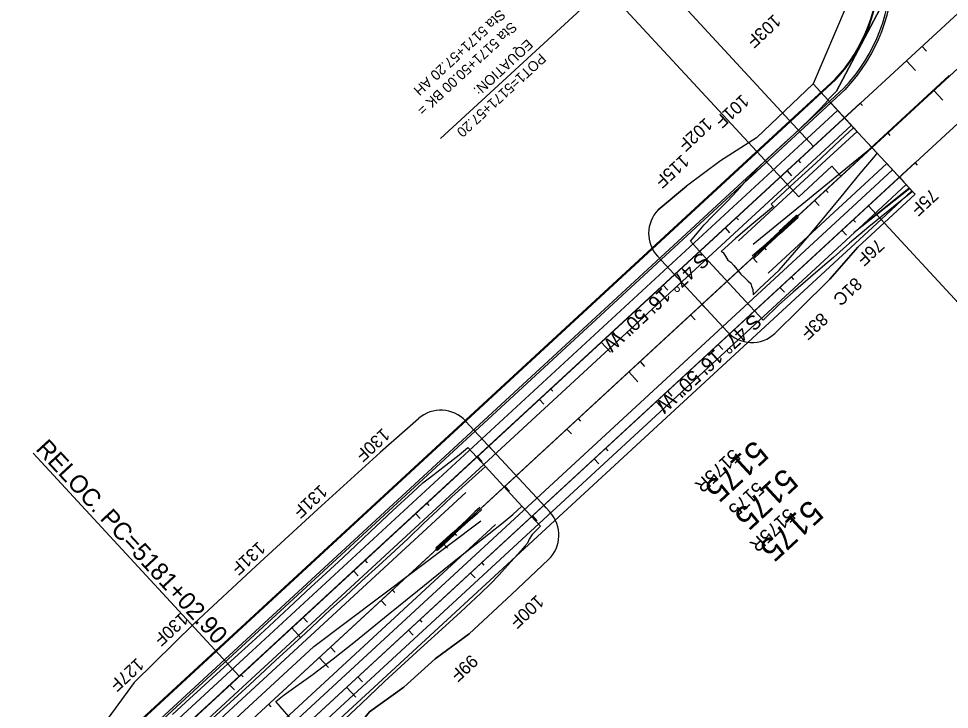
# Model space of a CAD drawing. Extents: x 2160876 to 2175990, y 601436 to 618246.
# Drawn here: x 2171264 to 2172369, y 613107 to 613927 of the extents above; entities that cross this region are included whole.
import ezdxf

# ---------------------------------------------------------------- set-up
doc = ezdxf.new("R2010")
doc.units = 0
for name, color, linetype in [('BNDY-ADJ', 7, 'Continuous'), ('BNDY-ADJ-TXT', 7, 'Continuous'), ('EX-UTIL-ELEC-TXT', 7, 'Continuous'), ('GN_Transparent 80', 7, 'Continuous'), ('RD_DTM_Major2', 7, 'Continuous'), ('RD_EX_BldgApp_Deck', 7, 'Continuous'), ('RD_EX_BldgApp_Sign', 7, 'Continuous'), ('RD_EX_BldgApp_Steps', 7, 'Continuous'), ('RD_EX_DV_TX_Prop', 7, 'Continuous'), ('RD_EX_Fence_Gate', 7, 'Continuous'), ('RD_EX_Parking_Conc', 7, 'Continuous'), ('RD_EX_RW', 7, 'Continuous'), ('RD_HC_Cl', 7, 'Continuous'), ('RD_HC_Data_Tic', 7, 'Continuous'), ('RD_HC_TX_Sta50', 7, 'Continuous'), ('RD_TX_RoadID', 7, 'Continuous')]:
    doc.layers.add(name, color=color, linetype=linetype)

msp = doc.modelspace()

# ---------------------------------------------------------------- linework, layer by layer
at = {"layer": 'BNDY-ADJ'}
for p, q in [((2172654, 614122.3), (2172239.9, 613739.9)), ((2172239.9, 613739.9), (2163704.8, 605858.6))]:
    msp.add_line(p, q, dxfattribs=at)
at = {"layer": 'BNDY-ADJ-TXT'}
for p, q in [((2172621.5, 614157.6), (2172207.3, 613775.1)), ((2172686.6, 614087), (2172272.5, 613704.6)), ((2172207.3, 613775.1), (2170395.2, 612101.8)), ((2172272.5, 613704.6), (2170460.3, 612031.3))]:
    msp.add_line(p, q, dxfattribs=at)
at = {"layer": 'EX-UTIL-ELEC-TXT'}
for p, q in [((2172233, 613855.1), (2172179.3, 613805.5)), ((2172233.7, 613854.4), (2172180, 613804.8)), ((2172235.9, 613817.9), (2172199.2, 613784)), ((2172179.3, 613805.5), (2170367.1, 612132.2)), ((2172244.1, 613809.1), (2172207.3, 613775.1)), ((2172180, 613804.8), (2170367.8, 612131.4)), ((2172252.2, 613800.2), (2172215.5, 613766.3)), ((2172199.2, 613784), (2170387, 612110.6)), ((2172207.3, 613775.1), (2170395.2, 612101.8)), ((2172215.5, 613766.3), (2170403.3, 612093)), ((2172301, 613747.3), (2172264.3, 613713.4)), ((2172317.3, 613729.7), (2172261.1, 613677.8)), ((2172309.2, 613738.5), (2172272.5, 613704.6)), ((2172321.6, 613725.1), (2172255.3, 613672.4)), ((2172264.3, 613713.4), (2170452.2, 612040.1)), ((2172272.5, 613704.6), (2170460.3, 612031.3)), ((2172261.1, 613677.8), (2170468.4, 612022.5))]:
    msp.add_line(p, q, dxfattribs=at)
msp.add_lwpolyline([(2172261.1, 613677.8), (2172306.9, 613714.8), (2172320.8, 613726)], dxfattribs=at)
for radius, start in [(193, 316.7496), (194, 317.041), (208, 316.7496)]:
    msp.add_arc((2172091.8, 613986.7), radius, start, 1.4209, dxfattribs=at)
at = {"layer": 'GN_Transparent 80'}
for p, q in [((2172243.2, 613844.1), (2172189.5, 613794.5)), ((2172244.9, 613842.5), (2172191, 613792.8)), ((2172189.5, 613794.5), (2170377.3, 612121.1)), ((2172191, 613792.8), (2170378.9, 612119.4)), ((2172150.6, 613659), (2172166.8, 613673.9)), ((2172168.3, 613672.2), (2172166.8, 613673.9)), ((2172152.2, 613657.3), (2172168.3, 613672.2)), ((2172142.8, 613647.8), (2172152.2, 613657.3)), ((2172137, 613642.3), (2172142.8, 613647.8)), ((2171813.7, 613343.8), (2171807.8, 613338.4)), ((2171796, 613331.6), (2171779.8, 613316.6)), ((2171807.8, 613338.4), (2171797.6, 613329.8)), ((2171797.6, 613329.8), (2171781.4, 613314.9)), ((2171781.4, 613314.9), (2171779.8, 613316.6))]:
    msp.add_line(p, q, dxfattribs=at)
for points in [[(2172134.5, 613645), (2172140.3, 613650.5), (2172150.6, 613659)], [(2171811.2, 613346.5), (2171805.3, 613341.1), (2171796, 613331.6)]]:
    msp.add_lwpolyline(points, dxfattribs=at)
msp.add_arc((2172091.8, 613986.7), 210.3, 316.7048, 1.4209, dxfattribs=at)
at = {"layer": 'RD_DTM_Major2'}
for p, q in [((2172350.1, 613841.6), (2172360.9, 613829.9)), ((2172276.6, 613773.8), (2172282, 613767.9)), ((2172208.4, 613710.8), (2172213.9, 613705)), ((2172135, 613643), (2172140.4, 613637.1)), ((2172061.5, 613575.2), (2172066.9, 613569.3)), ((2171988, 613507.3), (2171998.9, 613495.6)), ((2171914.6, 613439.5), (2171920, 613433.6)), ((2171841.1, 613371.6), (2171846.5, 613365.8)), ((2171767.6, 613303.8), (2171773.1, 613297.9)), ((2171694.2, 613236), (2171699.6, 613230.1)), ((2171620.7, 613168.1), (2171631.6, 613156.4))]:
    msp.add_line(p, q, dxfattribs=at)
at = {"layer": 'RD_EX_BldgApp_Deck'}
for p, q in [((2172166.4, 613674.3), (2172186.3, 613692.6)), ((2172166.4, 613674.3), (2172186.3, 613692.6)), ((2172168.7, 613671.9), (2172188.5, 613690.2)), ((2172188.5, 613690.2), (2172168.7, 613671.9)), ((2172169.7, 613676.6), (2172186.6, 613692.3)), ((2172171.3, 613674.9), (2172188.2, 613690.5)), ((2172177.8, 613684.1), (2172175.9, 613682.3)), ((2172178.1, 613684.4), (2172177.8, 613684.1)), ((2172179.4, 613682.4), (2172177.8, 613684.1)), ((2172180, 613686.1), (2172178.1, 613684.4)), ((2172179.7, 613682.7), (2172178.1, 613684.4)), ((2172180.3, 613686.4), (2172180, 613686.1)), ((2172181.6, 613684.4), (2172180, 613686.1)), ((2172182.2, 613688.2), (2172180.3, 613686.4)), ((2172181.9, 613684.7), (2172180.3, 613686.4)), ((2172182.5, 613688.5), (2172182.2, 613688.2)), ((2172183.8, 613686.5), (2172182.2, 613688.2)), ((2172184.4, 613690.2), (2172182.5, 613688.5)), ((2172184.1, 613686.7), (2172182.5, 613688.5)), ((2172186, 613688.5), (2172184.4, 613690.2)), ((2172186.3, 613688.8), (2172184.7, 613690.5)), ((2172188.5, 613690.2), (2172186.3, 613692.6)), ((2172186.5, 613692.3), (2172186.3, 613692.6)), ((2172188.5, 613690.2), (2172188.2, 613690.5)), ((2172166.4, 613674.3), (2172166.8, 613673.9)), ((2172166.8, 613673.9), (2172166.4, 613674.3)), ((2172166.8, 613673.9), (2172169.7, 613676.6)), ((2172169.7, 613676.6), (2172166.8, 613673.9)), ((2172168.3, 613672.2), (2172171.3, 613674.9)), ((2172168.3, 613672.2), (2172171.3, 613674.9)), ((2172171.2, 613678), (2172169.7, 613676.6)), ((2172171.3, 613674.9), (2172169.7, 613676.6)), ((2172171.5, 613678.3), (2172171.2, 613678)), ((2172172.7, 613676.3), (2172171.2, 613678)), ((2172173.4, 613680), (2172171.5, 613678.3)), ((2172173, 613676.6), (2172171.5, 613678.3)), ((2172173.7, 613680.3), (2172173.4, 613680)), ((2172174.9, 613678.3), (2172173.4, 613680)), ((2172175.6, 613682.1), (2172173.7, 613680.3)), ((2172175.2, 613678.6), (2172173.7, 613680.3)), ((2172175.9, 613682.3), (2172175.6, 613682.1)), ((2172177.2, 613680.4), (2172175.6, 613682.1)), ((2172177.4, 613680.6), (2172175.9, 613682.3)), ((2172168.7, 613671.9), (2172168.3, 613672.2)), ((2172168.7, 613671.9), (2172168.3, 613672.2)), ((2171779.5, 613317), (2171759.6, 613298.7)), ((2171779.5, 613317), (2171759.6, 613298.7)), ((2171776.9, 613313.9), (2171760, 613298.3)), ((2171778.5, 613312.2), (2171761.6, 613296.6)), ((2171781.7, 613314.6), (2171761.9, 613296.2)), ((2171761.9, 613296.2), (2171781.7, 613314.6)), ((2171770.7, 613308.2), (2171771, 613308.5)), ((2171771, 613308.5), (2171772.9, 613310.3)), ((2171772.6, 613306.8), (2171771, 613308.5)), ((2171772.9, 613310.3), (2171773.2, 613310.5)), ((2171774.5, 613308.5), (2171772.9, 613310.3)), ((2171773.2, 613310.5), (2171775.1, 613312.3)), ((2171774.8, 613308.8), (2171773.2, 613310.5)), ((2171775.1, 613312.3), (2171775.4, 613312.6)), ((2171776.7, 613310.6), (2171775.1, 613312.3)), ((2171775.4, 613312.6), (2171776.9, 613313.9)), ((2171777, 613310.9), (2171775.4, 613312.6)), ((2171779.8, 613316.6), (2171776.9, 613313.9)), ((2171776.9, 613313.9), (2171779.8, 613316.6)), ((2171778.5, 613312.2), (2171776.9, 613313.9)), ((2171781.4, 613314.9), (2171778.5, 613312.2)), ((2171781.4, 613314.9), (2171778.5, 613312.2)), ((2171779.5, 613317), (2171779.8, 613316.6)), ((2171779.8, 613316.6), (2171779.5, 613317)), ((2171781.7, 613314.6), (2171781.4, 613314.9)), ((2171781.7, 613314.6), (2171781.4, 613314.9)), ((2171761.9, 613296.2), (2171759.6, 613298.7)), ((2171759.9, 613298.4), (2171759.6, 613298.7)), ((2171763.5, 613298.4), (2171761.9, 613300.1)), ((2171762.2, 613300.4), (2171764.1, 613302.1)), ((2171763.8, 613298.6), (2171762.2, 613300.4)), ((2171764.1, 613302.1), (2171764.4, 613302.4)), ((2171765.7, 613300.4), (2171764.1, 613302.1)), ((2171764.4, 613302.4), (2171766.3, 613304.2)), ((2171766, 613300.7), (2171764.4, 613302.4)), ((2171766.3, 613304.2), (2171766.6, 613304.4)), ((2171767.9, 613302.4), (2171766.3, 613304.2)), ((2171766.6, 613304.4), (2171768.5, 613306.2)), ((2171768.2, 613302.7), (2171766.6, 613304.4)), ((2171768.5, 613306.2), (2171768.8, 613306.5)), ((2171770.1, 613304.5), (2171768.5, 613306.2)), ((2171768.8, 613306.5), (2171770.7, 613308.2)), ((2171770.4, 613304.7), (2171768.8, 613306.5)), ((2171772.3, 613306.5), (2171770.7, 613308.2)), ((2171761.9, 613296.2), (2171761.6, 613296.5))]:
    msp.add_line(p, q, dxfattribs=at)
for points in [[(2172171.3, 613674.9), (2172172.7, 613676.3), (2172173, 613676.6), (2172174.9, 613678.3), (2172175.2, 613678.6), (2172177.2, 613680.4), (2172177.4, 613680.6), (2172179.4, 613682.4), (2172179.7, 613682.7), (2172181.6, 613684.4), (2172181.9, 613684.7), (2172183.8, 613686.5), (2172184.1, 613686.7), (2172186, 613688.5), (2172186.3, 613688.8), (2172188.2, 613690.5)], [(2172186.6, 613692.3), (2172184.7, 613690.5), (2172184.4, 613690.2)], [(2172186.3, 613692.6), (2172186.5, 613692.3), (2172186.6, 613692.3)], [(2172188.2, 613690.5), (2172188.2, 613690.5), (2172188.5, 613690.2)], [(2171778.5, 613312.2), (2171777, 613310.9), (2171776.7, 613310.6), (2171774.8, 613308.8), (2171774.5, 613308.5), (2171772.6, 613306.8), (2171772.3, 613306.5), (2171770.4, 613304.7), (2171770.1, 613304.5), (2171768.2, 613302.7), (2171767.9, 613302.4), (2171766, 613300.7), (2171765.7, 613300.4), (2171763.8, 613298.6), (2171763.5, 613298.4), (2171761.6, 613296.6)], [(2171759.6, 613298.7), (2171759.9, 613298.4), (2171760, 613298.3)], [(2171760, 613298.3), (2171761.9, 613300.1), (2171762.2, 613300.4)], [(2171761.6, 613296.6), (2171761.6, 613296.5), (2171761.9, 613296.2)]]:
    msp.add_lwpolyline(points, dxfattribs=at)
for centre, radius, start, end in [((2172187.4, 613691.4), 1.67, 312.7195, 132.7195), ((2172187.4, 613691.4), 1.67, 312.7195, 132.7195), ((2172187.4, 613691.4), 1.27, 312.7195, 132.7195), ((2172187.4, 613691.4), 1.27, 312.7195, 132.7195), ((2171760.8, 613297.5), 1.67, 132.7195, 312.7195), ((2171760.8, 613297.5), 1.67, 132.7195, 312.7195), ((2171760.8, 613297.5), 1.27, 132.7195, 312.7195), ((2171760.8, 613297.5), 1.27, 132.7195, 312.7195)]:
    msp.add_arc(centre, radius, start, end, dxfattribs=at)
at = {"layer": 'RD_EX_BldgApp_Sign'}
for p, q in [((2172368.3, 613859.5), (2172269.3, 613768)), ((2172269.3, 613768), (2172135.6, 613658.5)), ((2171614.4, 613181.4), (2171812.6, 613330.3)), ((2170418.2, 612076.8), (2171614.4, 613181.4))]:
    msp.add_line(p, q, dxfattribs=at)
at = {"layer": 'RD_EX_BldgApp_Steps'}
for p, q in [((2172672.7, 614139.6), (2163700.6, 605854.7)), ((2172336, 613894.3), (2172341.5, 613888.4)), ((2172262.6, 613826.5), (2171525.8, 613146.1)), ((2172262.6, 613826.5), (2172265.3, 613823.5)), ((2172295.3, 613791.1), (2172298, 613788.1)), ((2172327.8, 613755.9), (2171568.5, 613054.8)), ((2172189.1, 613758.6), (2172191.8, 613755.7)), ((2172327.8, 613755.8), (2172330.5, 613752.9)), ((2172221.9, 613723.2), (2172224.6, 613720.3)), ((2172115.6, 613690.8), (2172118.3, 613687.8)), ((2172254.3, 613688), (2172257, 613685.1)), ((2172148.4, 613655.4), (2172151.1, 613652.4)), ((2172042.2, 613622.9), (2172044.9, 613620)), ((2172180.8, 613620.2), (2172183.6, 613617.2)), ((2172074.9, 613587.5), (2172077.6, 613584.6)), ((2171968.7, 613555.1), (2171974.1, 613549.2)), ((2172107.4, 613552.3), (2172110.1, 613549.4)), ((2172001.5, 613519.7), (2172006.9, 613513.8)), ((2171895.2, 613487.3), (2171897.9, 613484.3)), ((2172033.9, 613484.5), (2172039.3, 613478.6)), ((2171928, 613451.9), (2171930.7, 613448.9)), ((2171821.8, 613419.4), (2171824.5, 613416.5)), ((2171281.4, 613410.7), (2171525.8, 613146.1)), ((2171960.4, 613416.6), (2171963.2, 613413.7)), ((2171854.5, 613384), (2171857.2, 613381.1)), ((2171748.3, 613351.6), (2171751, 613348.6)), ((2171887, 613348.8), (2171889.7, 613345.9)), ((2171781, 613316.2), (2171783.8, 613313.2)), ((2171674.8, 613283.7), (2171677.5, 613280.8)), ((2171813.5, 613281), (2171816.2, 613278)), ((2171707.6, 613248.3), (2171710.3, 613245.4)), ((2171601.4, 613215.9), (2171606.8, 613210)), ((2171740, 613213.1), (2171742.7, 613210.2)), ((2171634.1, 613180.5), (2171639.5, 613174.6)), ((2171527.9, 613148.1), (2171530.6, 613145.1)), ((2171666.6, 613145.3), (2171672, 613139.4)), ((2171560.6, 613112.7), (2171563.4, 613109.7))]:
    msp.add_line(p, q, dxfattribs=at)
msp.add_arc((2246150.8, 532330.8), 110000, 132.719474, 133.343763, dxfattribs=at)
at = {"layer": 'RD_EX_Fence_Gate'}
for p, q in [((2172206.8, 613849.4), (2172139.8, 613785.1)), ((2172139.8, 613785.1), (2172097, 613757.8)), ((2172292.9, 613756.2), (2172260.3, 613791.4)), ((2172097, 613757.8), (2172056.7, 613727.8)), ((2172022.8, 613699.6), (2172056.7, 613727.8)), ((2172259.7, 613655.3), (2172327.9, 613718.3)), ((2172327.9, 613718.3), (2172325.5, 613720.9)), ((2172259.7, 613655.3), (2172226.5, 613617.6)), ((2172104.8, 613555.2), (2172022.2, 613644.6)), ((2172226.5, 613617.6), (2172190.9, 613582.4)), ((2172190.9, 613582.4), (2172161.4, 613553)), ((2171738.6, 613451.8), (2171693, 613411.5)), ((2171894.6, 613340.6), (2171794.5, 613449)), ((2171693, 613411.5), (2171618.9, 613344.3)), ((2171618.9, 613344.3), (2171545.4, 613276.7)), ((2171545.4, 613276.7), (2171472.5, 613208.6)), ((2171892.7, 613284.4), (2171848.8, 613242.9)), ((2171848.8, 613242.9), (2171798.8, 613196.4)), ((2171472.5, 613208.6), (2171401.2, 613138.6)), ((2171401.2, 613138.6), (2171341.1, 613056.4))]:
    msp.add_line(p, q, dxfattribs=at)
for points in [[(2172336.3, 614172), (2172273.2, 614089.5), (2172250.2, 614008.7), (2172246, 613941.4), (2172206.8, 613849.4)], [(2171798.8, 613196.4), (2171758.2, 613166.6), (2171721.2, 613133), (2171680.3, 613103.5), (2171648.3, 613064.5), (2171606.8, 613035.7)]]:
    msp.add_lwpolyline(points, dxfattribs=at)
for centre, start, end in [((2172051.6, 613671.8), 135.9419, 222.7195), ((2172134.2, 613582.3), 222.7195, 312.9079), ((2171765.1, 613421.9), 42.7195, 131.5105), ((2171865.2, 613313.5), 313.372, 42.7195)]:
    msp.add_arc(centre, 40, start, end, dxfattribs=at)
at = {"layer": 'RD_EX_Parking_Conc'}
for p, q in [((2171959.5, 613964.4), (2171764.8, 613784.6)), ((2172239.9, 613739.9), (2172229.2, 613751.5))]:
    msp.add_line(p, q, dxfattribs=at)
msp.add_lwpolyline([(2172229.2, 613751.5), (2172189.7, 613715.1), (2171959.5, 613964.4)], dxfattribs=at)
at = {"layer": 'RD_EX_RW'}
for p, q in [((2172206.8, 613849.4), (2172139.8, 613785.1)), ((2172260.3, 613791.4), (2172206.8, 613849.4)), ((2172224.5, 613830.2), (2172206.8, 613849.4)), ((2172206.8, 613849.4), (2172224.5, 613830.2)), ((2172254.9, 613797.3), (2172238.9, 613782.5)), ((2172260.3, 613791.4), (2172254.9, 613797.3)), ((2172139.8, 613785.1), (2172097, 613757.8)), ((2172283, 613766.9), (2172260.3, 613791.4)), ((2172097, 613757.8), (2172056.7, 613727.8)), ((2172325.5, 613720.9), (2172292.9, 613756.2)), ((2172056.7, 613727.8), (2172022.8, 613699.6)), ((2172259.7, 613655.3), (2172327.9, 613718.3)), ((2172325.5, 613720.9), (2172324.9, 613721.6)), ((2172327.9, 613718.3), (2172325.5, 613720.9)), ((2172226.5, 613617.6), (2172259.7, 613655.3)), ((2172022.2, 613644.6), (2172104.8, 613555.2)), ((2172190.9, 613582.4), (2172226.5, 613617.6)), ((2172161.4, 613553), (2172190.9, 613582.4)), ((2171738.6, 613451.8), (2171693, 613411.5)), ((2171894.6, 613340.6), (2171794.5, 613449)), ((2171693, 613411.5), (2171618.9, 613344.3)), ((2171861.3, 613347.9), (2171817.9, 613395)), ((2171618.9, 613344.3), (2171545.4, 613276.7)), ((2171545.4, 613276.7), (2171472.5, 613208.6)), ((2171848.8, 613242.9), (2171892.7, 613284.4)), ((2171798.8, 613196.4), (2171848.8, 613242.9)), ((2171472.5, 613208.6), (2171401.2, 613138.6)), ((2171401.2, 613138.6), (2171341.1, 613056.4))]:
    msp.add_line(p, q, dxfattribs=at)
for points in [[(2172349.7, 614161.7), (2172310.7, 614064.1), (2172297.2, 613959.5), (2172234.4, 613840.7)], [(2172234.4, 613840.7), (2172297.2, 613959.5), (2172310.7, 614064.1), (2172334.2, 614123)], [(2172263.8, 614056.5), (2172250.2, 614008.7), (2172246, 613941.4), (2172206.8, 613849.4)], [(2172224.5, 613830.2), (2172225.6, 613831.5), (2172234.4, 613840.7)], [(2172061.2, 613662.4), (2172071.8, 613674.8), (2172077.7, 613681.9), (2172087.1, 613692), (2172104.7, 613709.8), (2172117, 613722.9), (2172128.2, 613735.3), (2172141.5, 613749.8), (2172152.4, 613760.3), (2172172.8, 613779.2), (2172183.4, 613788.7), (2172202.7, 613807.1), (2172215.5, 613820), (2172224.5, 613830.2)], [(2172238.9, 613782.5), (2172209.9, 613755.4), (2172184.7, 613732.1), (2172157.2, 613706.5), (2172159.9, 613703.6), (2172131.8, 613680.5), (2172114.6, 613665.9), (2172097.6, 613650.4)], [(2172166.4, 613628.2), (2172184.9, 613649.1), (2172202.2, 613669.3), (2172223.3, 613694.5), (2172240.1, 613715.1), (2172262.5, 613742.8), (2172280.8, 613764.4), (2172283, 613766.9)], [(2172324.9, 613721.6), (2172310.7, 613710.1), (2172287.4, 613691.3), (2172273, 613679.7), (2172250.2, 613660.4), (2172231, 613643), (2172220.8, 613634.4), (2172203.8, 613619.8), (2172183, 613601.9), (2172166.3, 613587), (2172147.5, 613568.8)], [(2172147.5, 613568.8), (2172127, 613591.1), (2172082.8, 613638.9), (2172061.2, 613662.4)], [(2172147.5, 613568.8), (2172127, 613591.1), (2172082.8, 613638.9), (2172061.2, 613662.4)], [(2172097.6, 613650.4), (2172099.9, 613649), (2172103.2, 613643.8), (2172105.8, 613640.2), (2172109.2, 613637.5), (2172112.9, 613633.8), (2172116.4, 613629.4), (2172121.1, 613623.2), (2172125.8, 613619.1), (2172129.9, 613615.1), (2172132.9, 613612.2), (2172133.9, 613609.2), (2172135.1, 613605.3), (2172135.5, 613598.9)], [(2172135.5, 613598.9), (2172143.4, 613606.2), (2172166.4, 613628.2)], [(2171446.6, 613100.4), (2171462.4, 613115.2), (2171480.4, 613131.5), (2171499.2, 613148.8), (2171520.3, 613167.8), (2171540.7, 613186.3), (2171561.3, 613205.5), (2171585, 613227.5), (2171610.9, 613251.7), (2171624.3, 613264), (2171643.7, 613281.8), (2171663.2, 613300.3), (2171681.5, 613317.7), (2171708, 613342.9), (2171731.4, 613364.2), (2171743.5, 613375.5), (2171751.5, 613381.5), (2171763.9, 613391.2), (2171786.7, 613408.7), (2171797, 613417.6)], [(2171883.5, 613324.3), (2171861.3, 613347.9), (2171817.9, 613395), (2171797, 613417.6)], [(2171797, 613417.6), (2171817.9, 613395), (2171861.3, 613347.9), (2171883.5, 613324.3)], [(2171817.9, 613395), (2171802.2, 613380.7), (2171778.1, 613359.1), (2171761.4, 613343.3), (2171744.6, 613327.4), (2171726, 613309.3), (2171705.7, 613290.6), (2171691.2, 613277.2), (2171671.1, 613258.9), (2171652.3, 613241.6), (2171634.2, 613225.2), (2171604.3, 613197.2), (2171568.9, 613164.5), (2171538, 613135.8), (2171514.9, 613114.6), (2171495, 613096.6)], [(2171588, 613094.5), (2171579.5, 613104.1), (2171569.3, 613115.9), (2171579, 613124), (2171613.5, 613148.4), (2171637.1, 613166.7), (2171663.6, 613187.6), (2171702.4, 613219.4), (2171737.4, 613247.4), (2171776.9, 613279.4), (2171788.2, 613288.5), (2171807.1, 613303), (2171822.2, 613314.9), (2171839.2, 613328.5), (2171850.3, 613338.1), (2171861.3, 613347.9)], [(2171883.5, 613324.3), (2171873.3, 613314.3), (2171869.8, 613308.8), (2171867.9, 613303.9), (2171864.9, 613300.4), (2171859.9, 613294.8), (2171844.1, 613277.3), (2171834.4, 613266.4), (2171824, 613255.6), (2171812.4, 613244.7), (2171788.8, 613222.3), (2171766.4, 613201.9), (2171745.1, 613182.7), (2171727.2, 613166.1), (2171698.2, 613139.5), (2171670.6, 613113), (2171645.3, 613089.3)], [(2171606.8, 613035.7), (2171648.3, 613064.5), (2171680.3, 613103.5), (2171721.2, 613133), (2171758.2, 613166.6), (2171798.8, 613196.4)]]:
    msp.add_lwpolyline(points, dxfattribs=at)
for centre, start, end in [((2172051.6, 613671.8), 135.9419, 222.7195), ((2172134.2, 613582.3), 222.7195, 312.9079), ((2171765.1, 613421.9), 42.7195, 131.5105), ((2171865.2, 613313.5), 313.372, 42.7195)]:
    msp.add_arc(centre, 40, start, end, dxfattribs=at)
at = {"layer": 'RD_HC_Cl'}
for p, q in [((2172317.5, 613876.9), (2172328.4, 613865.1)), ((2172244.1, 613809.1), (2172249.5, 613803.2)), ((2172175.9, 613746.1), (2172181.3, 613740.2)), ((2172309.2, 613738.5), (2172314.6, 613732.7)), ((2172102.4, 613678.3), (2172107.8, 613672.4)), ((2172241, 613675.6), (2172246.4, 613669.7)), ((2172028.9, 613610.4), (2172034.4, 613604.5)), ((2172167.5, 613607.7), (2172173, 613601.9)), ((2171955.5, 613542.6), (2171966.3, 613530.8)), ((2172094.1, 613539.9), (2172099.5, 613534)), ((2171882, 613474.7), (2171887.4, 613468.9)), ((2172020.6, 613472.1), (2172031.5, 613460.3)), ((2171808.5, 613406.9), (2171814, 613401)), ((2171947.1, 613404.2), (2171952.6, 613398.3)), ((2171735.1, 613339.1), (2171740.5, 613333.2)), ((2171873.7, 613336.4), (2171879.1, 613330.5)), ((2171661.6, 613271.2), (2171667, 613265.3)), ((2171800.2, 613268.5), (2171805.6, 613262.7)), ((2171588.1, 613203.4), (2171599, 613191.6)), ((2171726.7, 613200.7), (2171732.2, 613194.8)), ((2171514.7, 613135.5), (2171520.1, 613129.7)), ((2171653.3, 613132.8), (2171664.1, 613121.1))]:
    msp.add_line(p, q, dxfattribs=at)
at = {"layer": 'RD_HC_TX_Sta50'}
for p, q in [((2172207.3, 613775.1), (2171994.4, 614005.8)), ((2172630.4, 613317), (2172272.5, 613704.6))]:
    msp.add_line(p, q, dxfattribs=at)
at = {"layer": 'RD_TX_RoadID'}
for p, q in [((2172227.8, 613826.7), (2172191, 613792.8)), ((2172259, 613792.9), (2172227.8, 613826.7)), ((2172191, 613792.8), (2170378.9, 612119.4)), ((2172259, 613792.9), (2172222.2, 613759)), ((2172222.2, 613759), (2172118.1, 613662.8)), ((2172294.3, 613754.7), (2172257.5, 613720.8)), ((2172294.3, 613754.7), (2172324.1, 613722.4)), ((2172257.5, 613720.8), (2172153.3, 613624.6)), ((2172324.1, 613722.4), (2172287.4, 613688.4)), ((2172287.4, 613688.4), (2170475.2, 612015.1)), ((2171794.8, 613364.3), (2170410.1, 612085.6)), ((2171830.1, 613326.1), (2170445.4, 612047.4))]:
    msp.add_line(p, q, dxfattribs=at)

# ---------------------------------------------------------------- texts
at = {"layer": 'RD_EX_BldgApp_Steps'}
for s, height, rotation, p in [('S 47° 16\' 50" W', 17, 222.7195, (2172073.8, 613650.4)), ('S 47° 16\' 50" W', 17, 222.7195, (2172136, 613577.4)), ('RELOC. PC=5181+02.90', 21, 312.7195, (2171283.4, 613415.2)), ('5175', 28, 222.7195, (2172137.3, 613427.6)), ('5175', 28, 222.7195, (2172172.5, 613394.5)), ('5175', 28, 222.7195, (2172202.5, 613357))]:
    msp.add_text(s, height=height, rotation=rotation, dxfattribs=at).set_placement(p)
at = {"layer": 'RD_EX_DV_TX_Prop'}
msp.add_text('5175', height=16, rotation=222.7195, dxfattribs=at).set_placement((2172139.8, 613377.9))
at = {"layer": 'RD_EX_Fence_Gate'}
for s, rotation, p in [('103F', 222.7195, (2172160.2, 613932.9)), ('101F', 222.7195, (2172122.4, 613837.9)), ('102F', 222.7195, (2172078.9, 613810)), ('115F', 222.7195, (2172051.3, 613766.4)), ('75F', 222.7195, (2172346.8, 613725.7)), ('76F', 222.7195, (2172282.6, 613666.4)), ('81C', 222.7195, (2172256.4, 613620.6)), ('83F', 222.7195, (2172216, 613578.7)), ('130F', 222.7195, (2171696.1, 613441.5)), ('131F', 222.7195, (2171622, 613374.4)), ('131F', 222.6747, (2171548.5, 613306.8)), ('100F', 222.7195, (2171879, 613243.5)), ('130F', 222.5962, (2171456.8, 613222.5)), ('127F', 222.5177, (2171404.4, 613168.6)), ('99F', 222.7195, (2171800.6, 613172.7))]:
    msp.add_text(s, height=15, rotation=rotation, dxfattribs=at).set_placement(p)
at = {"layer": 'RD_EX_Parking_Conc'}
for s, p in [('Sta 5171+57.20 AH', (2171835, 613938.5)), ('Sta 5171+50.00 BK = ', (2171848.6, 613923.8)), ('EQUATION:', (2171867.6, 613903.2)), ('POT1=5171+57.20', (2171883.1, 613886.4))]:
    msp.add_text(s, height=12, rotation=222.7195, dxfattribs=at).set_placement(p)
at = {"layer": 'RD_HC_Data_Tic'}
for p in [(2172111.3, 613417), (2172176.5, 613346.5)]:
    msp.add_text('5175R', height=16, rotation=222.7195, dxfattribs=at).set_placement(p)

doc.saveas('drawing.dxf')
